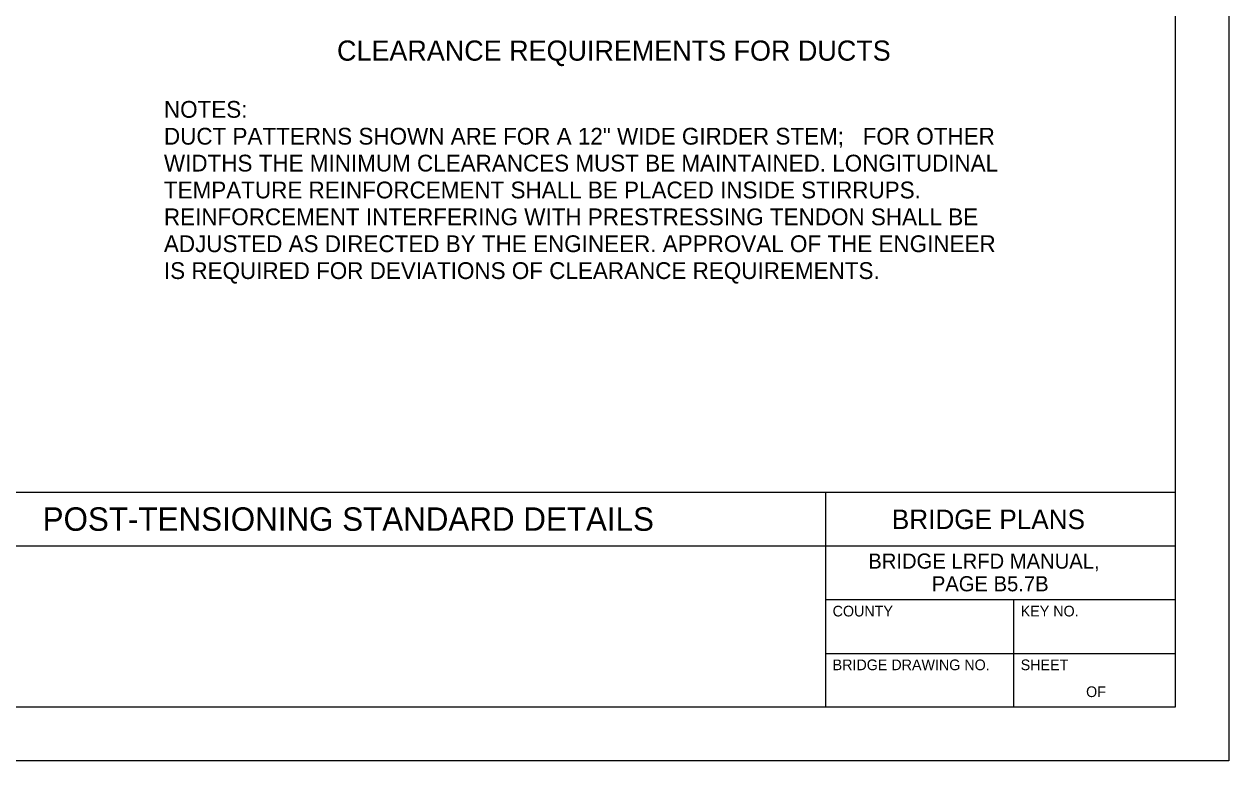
# Model space of a CAD drawing. Extents: x 0 to 22.7, y 0 to 15.7.
# Drawn here: x 15.19 to 22.67, y 0 to 4.57 of the extents above; entities that cross this region are included whole.
import ezdxf

# ---------------------------------------------------------------- set-up
doc = ezdxf.new("R2010")
doc.units = 0
for name, color, linetype in [('BORDER_ANNO_Cutsheet', 7, 'Continuous'), ('BRDG_ANNO_Anno-Sheet', 7, 'Continuous'), ('BRDG_ANNO_General-Notes', 7, 'Continuous')]:
    doc.layers.add(name, color=color, linetype=linetype)

msp = doc.modelspace()

# ---------------------------------------------------------------- linework, layer by layer
at = {"layer": 'BORDER_ANNO_Cutsheet'}
msp.add_lwpolyline([(0, 14.6667), (22.6667, 14.6667), (22.6667, 0), (0, 0)], close=True, dxfattribs=at)
at = {"layer": 'BRDG_ANNO_Anno-Sheet'}
for p, q in [((12.8333, 1.6667), (22.3333, 1.6667)), ((20.1667, 0.3333), (20.1667, 1.6667)), ((14.8333, 1.3333), (20.1667, 1.3333)), ((20.1667, 1.3333), (22.3333, 1.3333)), ((20.1667, 1), (22.3333, 1)), ((21.3333, 0.3333), (21.3333, 1)), ((20.1667, 0.6667), (22.3333, 0.6667))]:
    msp.add_line(p, q, dxfattribs=at)
msp.add_lwpolyline([(1, 14.3333), (22.3333, 14.3333), (22.3333, 0.3333), (1, 0.3333)], close=True, dxfattribs=at)

# ---------------------------------------------------------------- texts
for s, height, p in [('POST-TENSIONING STANDARD DETAILS', 0.145418, (15.3075, 1.4271)), ('BRIDGE PLANS', 0.12125, (20.5757, 1.4375)), ('BRIDGE LRFD MANUAL,', 0.09375, (20.4296, 1.1923)), ('PAGE B5.7B', 0.09375, (20.8237, 1.0517)), ('COUNTY', 0.06625, (20.2083, 0.8958)), ('KEY NO.', 0.06625, (21.375, 0.8958)), ('BRIDGE DRAWING NO.', 0.06625, (20.2083, 0.5625)), ('SHEET', 0.06625, (21.375, 0.5625)), ('OF', 0.06625, (21.7807, 0.3958))]:
    msp.add_text(s, height=height, dxfattribs=at).set_placement(p)
at = {"layer": 'BRDG_ANNO_General-Notes'}
for s, height, p in [('CLEARANCE REQUIREMENTS FOR DUCTS', 0.124948, (17.1337, 4.3426)), ('NOTES:', 0.10411, (16.0599, 3.9886)), ('DUCT PATTERNS SHOWN ARE FOR A 12" WIDE GIRDER STEM;   FOR OTHER', 0.104115, (16.0599, 3.822)), ('WIDTHS THE MINIMUM CLEARANCES MUST BE MAINTAINED. LONGITUDINAL', 0.104115, (16.0599, 3.6553)), ('TEMPATURE REINFORCEMENT SHALL BE PLACED INSIDE STIRRUPS.', 0.104115, (16.0599, 3.4886)), ('REINFORCEMENT INTERFERING WITH PRESTRESSING TENDON SHALL BE', 0.104115, (16.0599, 3.322)), ('ADJUSTED AS DIRECTED BY THE ENGINEER. APPROVAL OF THE ENGINEER', 0.104115, (16.0599, 3.1553)), ('IS REQUIRED FOR DEVIATIONS OF CLEARANCE REQUIREMENTS.', 0.104115, (16.0599, 2.9886))]:
    msp.add_text(s, height=height, dxfattribs=at).set_placement(p)

doc.saveas('drawing.dxf')
